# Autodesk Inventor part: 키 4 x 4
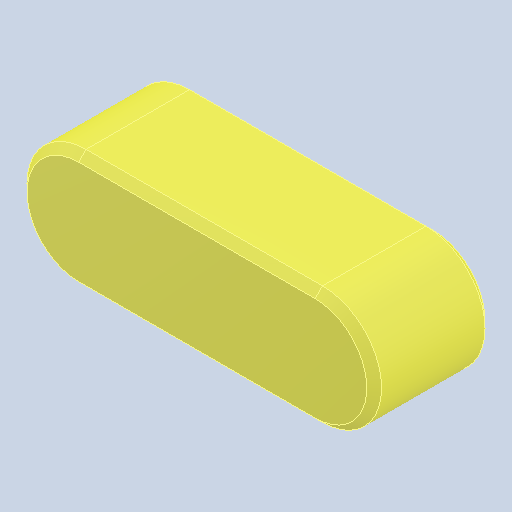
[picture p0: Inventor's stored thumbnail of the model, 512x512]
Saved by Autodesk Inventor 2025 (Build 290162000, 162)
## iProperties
Created: 2024-08
Part Number: 키 4 x 4
Material: 강철, 연강
Description: 키 및 해당 키홈
Document SubType Name: Modeling
Designer: samsung
Density: 7.86 g/cm^3
Appearance: 기본값
Author: jhkim
Sending System: Autodesk Inventor 2025
Preprocessor: ST-DEVELOPER v20
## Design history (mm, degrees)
feature "Solid1"
node "솔리드1"
